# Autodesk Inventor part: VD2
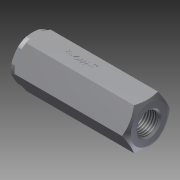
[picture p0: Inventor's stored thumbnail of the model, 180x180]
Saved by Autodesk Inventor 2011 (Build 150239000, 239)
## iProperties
Created: 2012-01
Part Number: VD2
Document SubType Name: Modeling
Designer: khramov
Density: 1 g/cm^3
Author: khramov
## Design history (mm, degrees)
derived "VD2_W1_30.ipt"
feature "Твердое тело1::VD2_W1_30.ipt" dims "d0" = 10
tag "Элемент создания маркировки1"
node "Твердое тело1"
